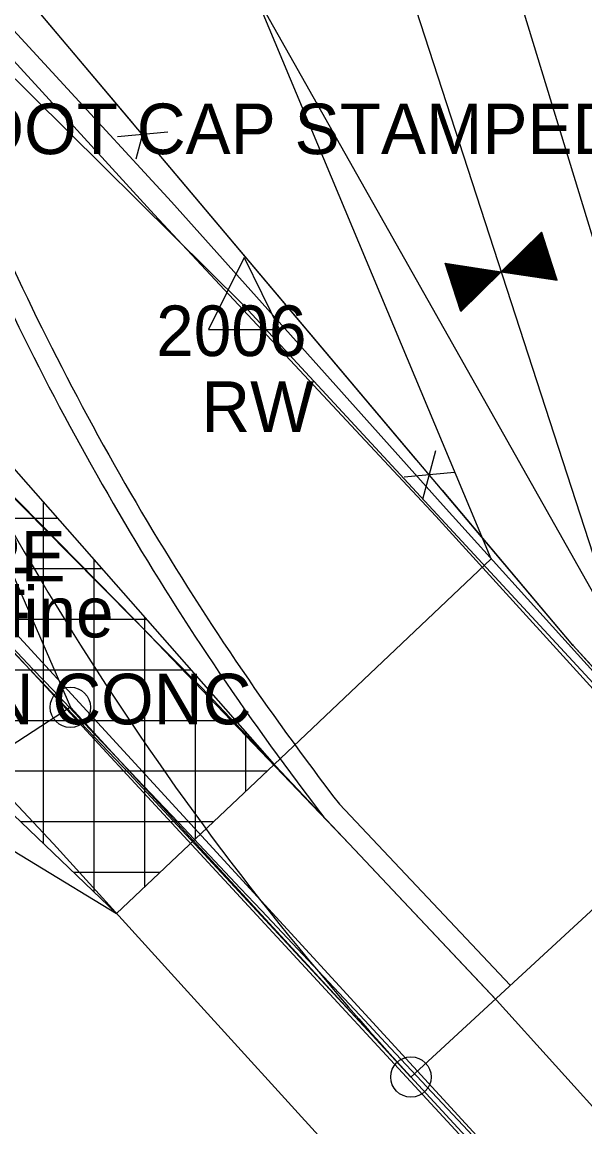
# Model space of a CAD drawing. Extents: x 1660112 to 1662239, y 668919 to 671377.
# Drawn here: x 1661383 to 1661438.6, y 670095.9 to 670205.1 of the extents above; entities that cross this region are included whole.
import ezdxf

# ---------------------------------------------------------------- set-up
doc = ezdxf.new("R2010")
doc.units = 0
for name, color, linetype in [('R_Axis', 7, 'Continuous'), ('R_Horz Alg', 7, 'Continuous'), ('R_Horz Alg Annot', 7, 'Continuous'), ('R_Proposed Const Limits_Cut', 7, 'Continuous'), ('R_Proposed Const Limits_Fill', 7, 'Continuous'), ('R_Proposed Const Limits_Hand', 7, 'Continuous'), ('R_Proposed Road_Lane', 7, 'Continuous'), ('R_Proposed Road_Shoulder', 7, 'Continuous'), ('R_ROW', 7, 'Continuous'), ('R_TCE', 7, 'Continuous'), ('S_DITCHLINE', 7, 'Continuous'), ('S_EDGE_PAVEMENT', 7, 'Continuous'), ('S_EXIST_ROW', 7, 'Continuous'), ('S_EXIST_ROW_ANNOT', 7, 'Continuous'), ('S_EXISTING_ALIGNMENT', 7, 'Continuous'), ('S_EXISTING_ALIGNMENT_ANNOT', 7, 'Continuous'), ('S_FENCE', 7, 'Continuous'), ('S_MSC_PT_SYM', 7, 'Continuous'), ('S_PAVEMENT_CROWN', 7, 'Continuous'), ('S_PRIMARY_CTL_ANNOT', 7, 'Continuous'), ('S_SANITARY_SEWER_ANNOT', 7, 'Continuous')]:
    doc.layers.add(name, color=color, linetype=linetype)

msp = doc.modelspace()

# ---------------------------------------------------------------- linework, layer by layer
at = {"layer": 'R_Axis'}
for p, q in [((1661385.12, 670123.91), (1661385.12, 670157.62)), ((1661351.48, 670156.1), (1661386.46, 670156.1)), ((1661390.12, 670119.13), (1661390.12, 670151.94)), ((1661356.71, 670151.1), (1661390.87, 670151.1)), ((1661361.93, 670146.1), (1661395.27, 670146.1)), ((1661395.12, 670119.66), (1661395.12, 670146.26)), ((1661367.16, 670141.1), (1661399.67, 670141.1)), ((1661400.12, 670124.39), (1661400.12, 670140.59)), ((1661372.39, 670136.1), (1661404.07, 670136.1)), ((1661405.12, 670129.11), (1661405.12, 670134.91)), ((1661377.61, 670131.1), (1661407.23, 670131.1)), ((1661382.84, 670126.1), (1661401.94, 670126.1)), ((1661388.06, 670121.1), (1661396.65, 670121.1))]:
    msp.add_line(p, q, dxfattribs=at)
msp.add_lwpolyline([(1661320.12, 670186.1), (1661341.66, 670206.99), (1661407.91, 670131.74), (1661392.33, 670117.02)], close=True, dxfattribs=at)
at = {"layer": 'R_Horz Alg'}
for centre, radius, start, end in [((1655846.99, 664877.91), 7639.44, 42.561815, 45.430038), ((1661637.47, 670300), 293.82, 203.4717, 222.6711), ((1661637.47, 670300), 293.82, 203.4717, 222.6711)]:
    msp.add_arc(centre, radius, start, end, dxfattribs=at)
at = {"layer": 'R_Horz Alg Annot'}
for p, q in [((1661344.44, 670185.98), (1661473.81, 670045.11)), ((1661367.97, 670182.97), (1661387.76, 670137.39)), ((1661387.76, 670137.39), (1661421.44, 670100.85))]:
    msp.add_line(p, q, dxfattribs=at)
for points in [[(1661421.44, 670100.85), (1661511.61, 670183.97)], [(1661387.76, 670137.39), (1661287.2, 670071.9)]]:
    msp.add_lwpolyline(points, dxfattribs=at)
for centre in [(1661387.76, 670137.39), (1661421.44, 670100.85)]:
    msp.add_circle(centre, 2, dxfattribs=at)
at = {"layer": 'R_Proposed Const Limits_Cut'}
msp.add_lwpolyline([(1661407.91, 670131.74), (1661429.38, 670152.08), (1661397.79, 670227.54)], dxfattribs=at)
at = {"layer": 'R_Proposed Const Limits_Fill'}
msp.add_lwpolyline([(1661278.26, 670196.37), (1661284.16, 670190.75), (1661286.76, 670188.4), (1661293.84, 670181.4), (1661297.09, 670178.04), (1661304.19, 670170.65), (1661392.33, 670117.02)], dxfattribs=at)
at = {"layer": 'R_Proposed Const Limits_Hand'}
msp.add_line((1661406.71, 670206.71), (1661451.04, 670128.13), dxfattribs=at)
at = {"layer": 'R_Proposed Road_Lane'}
msp.add_lwpolyline([(1661352.12, 670188.73), (1661394.19, 670145.97), (1661415.33, 670123.89), (1661429.8, 670108.55)], dxfattribs=at)
msp.add_arc((1661637.47, 670300), 283.82, 203.4717, 217.6784, dxfattribs=at)
at = {"layer": 'R_Proposed Road_Shoulder'}
msp.add_lwpolyline([(1661414.37, 670127.82), (1661431.25, 670109.93)], dxfattribs=at)
msp.add_arc((1661637.47, 670300), 281.82, 203.4717, 217.6583, dxfattribs=at)
at = {"layer": 'R_ROW'}
msp.add_lwpolyline([(1661492.29, 670317.34), (1661506.22, 670273.91), (1661412.98, 670233.91), (1661445.83, 670132.9)], dxfattribs=at)
at = {"layer": 'R_TCE'}
msp.add_line((1661422.81, 670238.12), (1661459.43, 670118.19), dxfattribs=at)
at = {"layer": 'S_DITCHLINE'}
for points in [[(1661494.51, 670072.98), (1661481.63, 670087.01), (1661468.75, 670101.04), (1661468.56, 670102.05), (1661459.49, 670114.59), (1661450.42, 670127.12), (1661437.16, 670141.71), (1661423.9, 670156.29), (1661409.97, 670171.2), (1661396.04, 670186.11), (1661384.96, 670198.23), (1661373.87, 670210.36), (1661354.32, 670219.23), (1661344.06, 670230.9), (1661333.8, 670242.57), (1661320.4, 670253.01)], [(1661495.46, 670073.89), (1661482.85, 670088.25), (1661470.25, 670102.6), (1661470.41, 670103.23), (1661460.8, 670115.6), (1661451.19, 670127.97), (1661437.9, 670142.65), (1661424.62, 670157.34), (1661411.2, 670172.34), (1661397.77, 670187.35), (1661386.72, 670199.36), (1661375.66, 670211.37), (1661356.56, 670219.75), (1661346.24, 670231.99), (1661335.91, 670244.22), (1661322, 670253.4)]]:
    msp.add_lwpolyline(points, dxfattribs=at)
at = {"layer": 'S_EDGE_PAVEMENT'}
for points in [[(1661528.89, 670006.64), (1661525.81, 670010.93), (1661521.19, 670007.06), (1661512.12, 670017.42), (1661503.06, 670027.78), (1661494.14, 670038.45), (1661485.22, 670049.12), (1661475.65, 670058.13), (1661469.7, 670064.69), (1661453.26, 670082.63), (1661441.58, 670095.54), (1661429.9, 670108.45), (1661415.33, 670123.89), (1661400.76, 670139.32), (1661387.62, 670152.61), (1661374.47, 670165.9), (1661358.81, 670181.9), (1661343.14, 670197.9), (1661339.48, 670201.44), (1661329.75, 670211.05), (1661320.02, 670220.65), (1661304.77, 670236.19)], [(1661507.57, 669985.17), (1661503.63, 669990.55), (1661503.83, 669996.41), (1661492.59, 670008.33), (1661484.98, 670015.56), (1661475.91, 670025.37), (1661466.84, 670035.18), (1661454.4, 670049.73), (1661445.95, 670059), (1661437.51, 670068.28), (1661425.39, 670081.13), (1661413.28, 670093.99), (1661399.68, 670108.94), (1661386.08, 670123.89), (1661373.13, 670137.66), (1661360.18, 670151.43), (1661345.14, 670167.24), (1661330.11, 670183.04), (1661325.69, 670187.24), (1661316.74, 670196.41), (1661307.8, 670205.57), (1661291.28, 670222.16)]]:
    msp.add_lwpolyline(points, dxfattribs=at)
at = {"layer": 'S_EXIST_ROW'}
for p, q in [((1661404.92, 670177.11), (1660401.45, 671169.67)), ((1661404.94, 670181.84), (1661401.41, 670174.75)), ((1661404.94, 670181.84), (1661408.43, 670174.75)), ((1661404.92, 670177.11), (1661404.92, 670177.11)), ((1661622.22, 669942.24), (1661404.92, 670177.11)), ((1661401.41, 670174.75), (1661408.43, 670174.75))]:
    msp.add_line(p, q, dxfattribs=at)
for radius in [0.12, 0.06]:
    msp.add_circle((1661404.92, 670177.11), radius, dxfattribs=at)
at = {"layer": 'S_EXISTING_ALIGNMENT'}
msp.add_line((1661613.41, 669892.86), (1661376.17, 670149.3), dxfattribs=at)
at = {"layer": 'S_FENCE'}
for p, q in [((1661437.44, 670143.55), (1661353.95, 670242.57)), ((1661394.26, 670191.59), (1661395.54, 670196.42)), ((1661394.26, 670191.59), (1661395.54, 670196.42)), ((1661397.39, 670194.23), (1661392.41, 670193.78)), ((1661397.39, 670194.23), (1661392.41, 670193.78)), ((1661434.18, 670184.21), (1661435.66, 670179.66)), ((1661434.26, 670184.29), (1661435.77, 670179.64)), ((1661434.34, 670184.36), (1661435.88, 670179.62)), ((1661433.06, 670183.11), (1661434.11, 670179.89)), ((1661433.14, 670183.19), (1661434.22, 670179.87)), ((1661433.22, 670183.26), (1661434.33, 670179.85)), ((1661433.3, 670183.34), (1661434.44, 670179.84)), ((1661433.38, 670183.42), (1661434.55, 670179.82)), ((1661433.46, 670183.5), (1661434.66, 670179.8)), ((1661433.54, 670183.58), (1661434.77, 670179.79)), ((1661433.62, 670183.66), (1661434.88, 670179.77)), ((1661433.7, 670183.74), (1661434.99, 670179.75)), ((1661433.78, 670183.81), (1661435.1, 670179.74)), ((1661433.86, 670183.89), (1661435.22, 670179.72)), ((1661433.94, 670183.97), (1661435.33, 670179.71)), ((1661434.02, 670184.05), (1661435.44, 670179.69)), ((1661434.1, 670184.13), (1661435.55, 670179.67)), ((1661431.95, 670182.01), (1661432.56, 670180.12)), ((1661432.03, 670182.09), (1661432.67, 670180.1)), ((1661432.11, 670182.17), (1661432.78, 670180.09)), ((1661432.19, 670182.24), (1661432.89, 670180.07)), ((1661432.27, 670182.32), (1661433, 670180.05)), ((1661432.35, 670182.4), (1661433.11, 670180.04)), ((1661432.43, 670182.48), (1661433.23, 670180.02)), ((1661432.51, 670182.56), (1661433.34, 670180)), ((1661432.58, 670182.64), (1661433.45, 670179.99)), ((1661432.66, 670182.72), (1661433.56, 670179.97)), ((1661432.74, 670182.79), (1661433.67, 670179.95)), ((1661432.82, 670182.87), (1661433.78, 670179.94)), ((1661432.9, 670182.95), (1661433.89, 670179.92)), ((1661432.98, 670183.03), (1661434, 670179.9)), ((1661424.92, 670181.27), (1661426.44, 670176.58)), ((1661425.03, 670181.25), (1661426.52, 670176.66)), ((1661425.14, 670181.24), (1661426.6, 670176.74)), ((1661425.25, 670181.22), (1661426.68, 670176.82)), ((1661425.36, 670181.2), (1661426.76, 670176.9)), ((1661425.47, 670181.19), (1661426.84, 670176.98)), ((1661425.58, 670181.17), (1661426.92, 670177.05)), ((1661425.69, 670181.15), (1661427, 670177.13)), ((1661425.8, 670181.14), (1661427.08, 670177.21)), ((1661425.91, 670181.12), (1661427.16, 670177.29)), ((1661426.02, 670181.1), (1661427.24, 670177.37)), ((1661426.13, 670181.09), (1661427.32, 670177.45)), ((1661426.24, 670181.07), (1661427.4, 670177.52)), ((1661426.35, 670181.05), (1661427.48, 670177.6)), ((1661426.47, 670181.04), (1661427.56, 670177.68)), ((1661426.58, 670181.02), (1661427.64, 670177.76)), ((1661426.69, 670181), (1661427.72, 670177.84)), ((1661426.8, 670180.99), (1661427.8, 670177.92)), ((1661426.91, 670180.97), (1661427.87, 670178)), ((1661427.02, 670180.95), (1661427.95, 670178.07)), ((1661427.13, 670180.94), (1661428.03, 670178.15)), ((1661427.24, 670180.92), (1661428.11, 670178.23)), ((1661427.35, 670180.9), (1661428.19, 670178.31)), ((1661430.83, 670180.91), (1661431.01, 670180.35)), ((1661430.91, 670180.99), (1661431.12, 670180.34)), ((1661430.99, 670181.07), (1661431.24, 670180.32)), ((1661431.07, 670181.15), (1661431.35, 670180.3)), ((1661431.15, 670181.22), (1661431.46, 670180.29)), ((1661431.23, 670181.3), (1661431.57, 670180.27)), ((1661431.31, 670181.38), (1661431.68, 670180.25)), ((1661431.39, 670181.46), (1661431.79, 670180.24)), ((1661431.47, 670181.54), (1661431.9, 670180.22)), ((1661431.55, 670181.62), (1661432.01, 670180.2)), ((1661431.63, 670181.7), (1661432.12, 670180.19)), ((1661431.71, 670181.77), (1661432.23, 670180.17)), ((1661431.79, 670181.85), (1661432.34, 670180.15)), ((1661431.87, 670181.93), (1661432.45, 670180.14)), ((1661427.46, 670180.89), (1661428.27, 670178.39)), ((1661427.57, 670180.87), (1661428.35, 670178.47)), ((1661427.68, 670180.85), (1661428.43, 670178.54)), ((1661427.79, 670180.84), (1661428.51, 670178.62)), ((1661427.9, 670180.82), (1661428.59, 670178.7)), ((1661428.01, 670180.8), (1661428.67, 670178.78)), ((1661428.12, 670180.79), (1661428.75, 670178.86)), ((1661428.23, 670180.77), (1661428.83, 670178.94)), ((1661428.34, 670180.75), (1661428.91, 670179.02)), ((1661428.46, 670180.74), (1661428.99, 670179.09)), ((1661428.57, 670180.72), (1661429.07, 670179.17)), ((1661428.68, 670180.7), (1661429.15, 670179.25)), ((1661428.79, 670180.69), (1661429.23, 670179.33)), ((1661428.9, 670180.67), (1661429.31, 670179.41)), ((1661429.01, 670180.65), (1661429.39, 670179.49)), ((1661429.12, 670180.64), (1661429.47, 670179.57)), ((1661429.23, 670180.62), (1661429.55, 670179.64)), ((1661429.34, 670180.61), (1661429.63, 670179.72)), ((1661429.45, 670180.59), (1661429.71, 670179.8)), ((1661429.56, 670180.57), (1661429.79, 670179.88)), ((1661429.67, 670180.56), (1661429.87, 670179.96)), ((1661429.78, 670180.54), (1661429.95, 670180.04)), ((1661429.89, 670180.52), (1661430.03, 670180.11)), ((1661430, 670180.51), (1661430.1, 670180.19)), ((1661430.11, 670180.49), (1661430.18, 670180.27)), ((1661430.22, 670180.47), (1661430.26, 670180.35)), ((1661430.33, 670180.46), (1661430.34, 670180.43)), ((1661430.43, 670180.52), (1661430.46, 670180.44)), ((1661430.51, 670180.6), (1661430.57, 670180.42)), ((1661430.59, 670180.68), (1661430.68, 670180.4)), ((1661430.67, 670180.75), (1661430.79, 670180.39)), ((1661430.75, 670180.83), (1661430.9, 670180.37)), ((1661422.62, 670157.95), (1661423.9, 670162.78)), ((1661422.62, 670157.95), (1661423.9, 670162.78)), ((1661425.75, 670160.59), (1661420.77, 670160.14)), ((1661425.75, 670160.59), (1661420.77, 670160.14)), ((1661463.18, 670115.3), (1661437.44, 670143.55))]:
    msp.add_line(p, q, dxfattribs=at)
for points in [[(1661393.97, 670195.1), (1661381.08, 670210.39)], [(1661393.97, 670195.1), (1661381.08, 670210.39)], [(1661421.97, 670161.89), (1661396.19, 670192.47)], [(1661421.97, 670161.89), (1661396.19, 670192.47)], [(1661437.44, 670143.55), (1661424.55, 670158.84)], [(1661437.44, 670143.55), (1661424.55, 670158.84)], [(1661447.01, 670133.04), (1661437.44, 670143.55)], [(1661447.01, 670133.04), (1661437.44, 670143.55)]]:
    msp.add_lwpolyline(points, dxfattribs=at)
for points in [[(1661434.35, 670184.37), (1661430.37, 670180.45), (1661435.89, 670179.62)], [(1661424.84, 670181.28), (1661430.37, 670180.45), (1661426.38, 670176.53)]]:
    msp.add_lwpolyline(points, close=True, dxfattribs=at)
at = {"layer": 'S_MSC_PT_SYM'}
msp.add_lwpolyline([(1661437.44, 670143.55), (1661437.44, 670143.6), (1661437.44, 670143.55), (1661437.39, 670143.55), (1661437.44, 670143.55), (1661437.44, 670143.5), (1661437.44, 670143.55), (1661437.49, 670143.55)], dxfattribs=at)
at = {"layer": 'S_PAVEMENT_CROWN'}
msp.add_lwpolyline([(1661518.06, 669996.03), (1661505.4, 670009.31), (1661492.74, 670022.59), (1661480.19, 670036.99), (1661467.64, 670051.39), (1661473.76, 670044.39), (1661461.34, 670057.98), (1661445.4, 670075.38), (1661443.99, 670076.39), (1661432.69, 670088.65), (1661421.39, 670100.9), (1661407.48, 670115.88), (1661393.57, 670130.85), (1661380.41, 670144.59), (1661367.25, 670158.33), (1661351.88, 670174.26), (1661336.51, 670190.18), (1661332.38, 670194.36), (1661323.21, 670203.51), (1661314.05, 670212.66), (1661297.56, 670228.68)], dxfattribs=at)

# ---------------------------------------------------------------- texts
at = {"layer": 'S_EXIST_ROW_ANNOT'}
for s, p in [('2006', (1661396.24, 670172.11)), ('RW', (1661400.71, 670164.61))]:
    msp.add_text(s, height=5, dxfattribs=at).set_placement(p)
at = {"layer": 'S_EXISTING_ALIGNMENT_ANNOT'}
msp.add_text('2010 Centerline', height=5, dxfattribs=at).set_placement((1661344.83, 670144.3))
at = {"layer": 'S_PRIMARY_CTL_ANNOT'}
for s, p in [('PD:STD ARDOT CAP STAMPED PN:3', (1661342.69, 670192.07)), ('PD:CHISELED SQUARE IN CONC', (1661300.89, 670135.71))]:
    msp.add_text(s, height=5, dxfattribs=at).set_placement(p)
at = {"layer": 'S_SANITARY_SEWER_ANNOT'}
for p in [(1661292.56, 670149.83), (1661289.08, 670146.19)]:
    msp.add_text('4IN PLASTIC INVERT OF PIPE', height=5, dxfattribs=at).set_placement(p)

doc.saveas('drawing.dxf')
